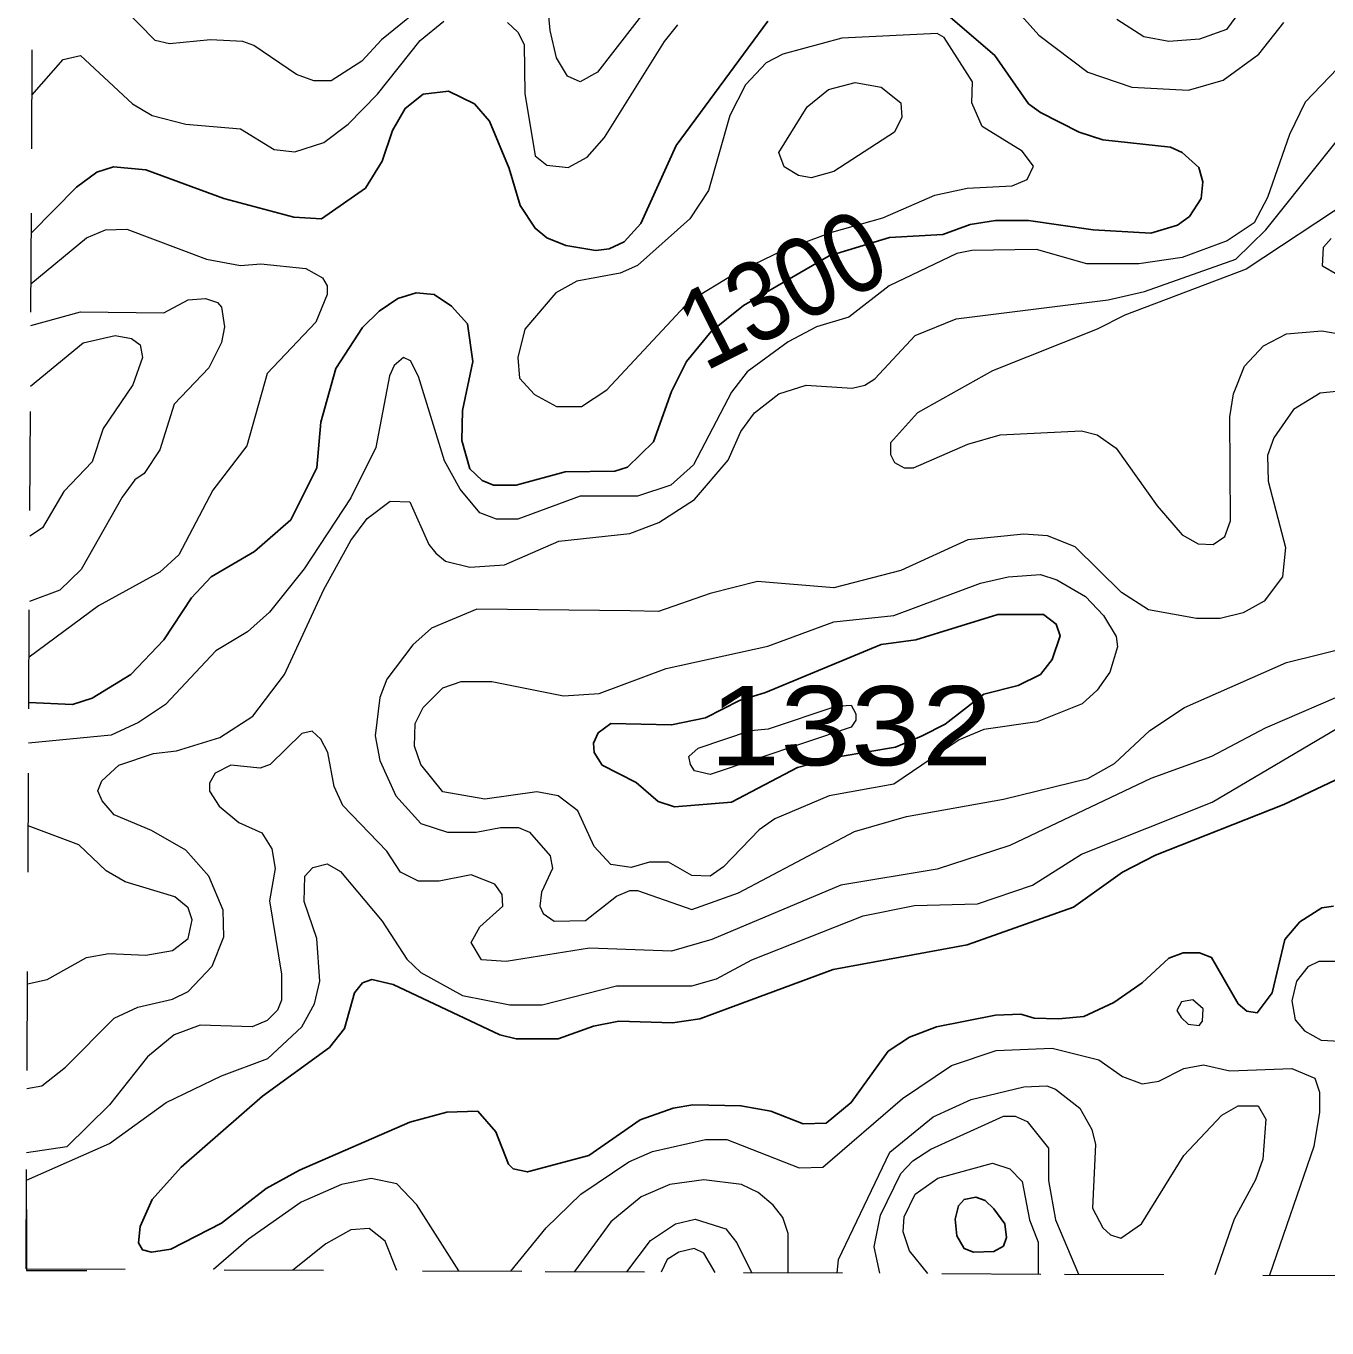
# Model space of a CAD drawing. Extents: x 577 to 602.9, y 7483.8 to 7511.6.
# Drawn here: x 577.007 to 578.319, y 7483.867 to 7485.181 of the extents above; entities that cross this region are included whole.
import ezdxf
from ezdxf.enums import TextEntityAlignment as Align

# ---------------------------------------------------------------- set-up
doc = ezdxf.new("R2010")
doc.units = 0
doc.header["$LTSCALE"] = 0.032
doc.linetypes.add('SHORT_DASHED', pattern=[2.7, 1.5, -1.2])
for name, color, linetype, lineweight in [('1', 7, 'Continuous', 25), ('2', 7, 'Continuous', 13), ('62', 7, 'SHORT_DASHED', 13), ('63', 7, 'Continuous', 13)]:
    doc.layers.add(name, color=color, linetype=linetype, lineweight=lineweight)
doc.layers.add('61', color=7, linetype='Continuous')

msp = doc.modelspace()

# ---------------------------------------------------------------- linework, layer by layer
at = {"layer": '1'}
for points in [[(577.9179, 7485.2079), (577.9839, 7485.1507), (578.0181, 7485.1022), (578.03, 7485.0934), (578.069, 7485.0735), (578.0928, 7485.0656), (578.1612, 7485.0584), (578.1731, 7485.0529), (578.1898, 7485.0377), (578.1938, 7485.0234), (578.1922, 7485.0067), (578.1803, 7484.9884), (578.1684, 7484.9797), (578.1413, 7484.9717), (578.0833, 7484.9749), (578.0181, 7484.9845), (577.9847, 7484.9845), (577.9592, 7484.9805), (577.9314, 7484.9702), (577.8777, 7484.9673), (577.8168, 7484.9486), (577.7304, 7484.8988), (577.698, 7484.8725), (577.673, 7484.8421), (577.6579, 7484.8119), (577.6396, 7484.761), (577.6133, 7484.7356), (577.6006, 7484.7316), (577.5505, 7484.7308), (577.5012, 7484.7173), (577.4782, 7484.7173), (577.467, 7484.7221), (577.4543, 7484.734), (577.4464, 7484.7626), (577.4471, 7484.7928), (577.4575, 7484.8421), (577.4519, 7484.8803), (577.436, 7484.8978), (577.4185, 7484.9097), (577.4002, 7484.9113), (577.3819, 7484.9057), (577.3629, 7484.893), (577.3462, 7484.8763), (577.3191, 7484.835), (577.304, 7484.7809), (577.3, 7484.7348), (577.2738, 7484.6823), (577.2372, 7484.6505), (577.1935, 7484.625), (577.1736, 7484.6036), (577.1458, 7484.5614), (577.1124, 7484.5264), (577.0734, 7484.5026), (577.0535, 7484.4962), (577.0095, 7484.4983)], [(577.012, 7484.9716), (577.0575, 7485.0179), (577.0782, 7485.033), (577.0949, 7485.0385), (577.1275, 7485.0354), (577.2062, 7485.0067), (577.277, 7484.9876), (577.3048, 7484.9861), (577.3493, 7485.0171), (577.366, 7485.0441), (577.3764, 7485.0751), (577.3891, 7485.0974), (577.4074, 7485.1117), (577.4328, 7485.1149), (577.4591, 7485.1022), (577.4742, 7485.0847), (577.4941, 7485.0369), (577.5052, 7484.9996), (577.5203, 7484.9765), (577.5322, 7484.967), (577.5513, 7484.959), (577.5815, 7484.9542), (577.595, 7484.9558), (577.6102, 7484.963), (577.6269, 7484.9813), (577.6626, 7485.06), (577.7549, 7485.1856)], [(578.0101, 7484.1837), (577.9847, 7484.1829), (577.925, 7484.171), (577.898, 7484.1607), (577.8765, 7484.1464), (577.8392, 7484.0947), (577.8137, 7484.074), (577.7907, 7484.0732), (577.7581, 7484.0859), (577.7278, 7484.0915), (577.6793, 7484.0923), (577.6595, 7484.0891), (577.6261, 7484.0772), (577.5744, 7484.0414), (577.5124, 7484.0247), (577.498, 7484.0279), (577.4933, 7484.0326), (577.4805, 7484.0652), (577.4623, 7484.0859), (577.4312, 7484.0851), (577.3939, 7484.0748), (577.2825, 7484.0263), (577.2491, 7484.008), (577.2038, 7483.973), (577.1529, 7483.9468), (577.1331, 7483.9436), (577.1243, 7483.946), (577.1203, 7483.9531), (577.1219, 7483.9698), (577.1338, 7483.9969), (577.1633, 7484.0295), (577.2452, 7484.101), (577.3128, 7484.1503), (577.3279, 7484.1694), (577.3382, 7484.2052), (577.3462, 7484.2155), (577.3557, 7484.2187), (577.3772, 7484.2139), (577.4845, 7484.163), (577.5012, 7484.1591), (577.5434, 7484.1591), (577.5791, 7484.1718), (577.6046, 7484.1766), (577.6587, 7484.175), (577.6865, 7484.179), (577.8209, 7484.229), (577.9561, 7484.2537), (578.0634, 7484.2919), (578.1127, 7484.3269), (578.1461, 7484.3443), (578.2757, 7484.3952), (578.4833, 7484.4938)], [(578.3258, 7484.2927), (578.3139, 7484.2911), (578.2916, 7484.2768), (578.2765, 7484.2593), (578.2638, 7484.2052), (578.2487, 7484.1853), (578.2383, 7484.1869), (578.2296, 7484.1941), (578.2026, 7484.241), (578.1906, 7484.2457), (578.1739, 7484.2457), (578.1596, 7484.2402), (578.1326, 7484.2155), (578.104, 7484.1957), (578.0737, 7484.1813), (578.0483, 7484.179), (578.0236, 7484.1797), (578.0101, 7484.1837)]]:
    msp.add_lwpolyline(points, dxfattribs=at)
for points in [[(577.7527, 7484.5084), (577.8694, 7484.5567), (577.9044, 7484.5614), (577.9871, 7484.5869), (578.0332, 7484.5869), (578.0459, 7484.5773), (578.0499, 7484.5654), (578.0419, 7484.5416), (578.03, 7484.5264), (578.0077, 7484.5153), (577.9728, 7484.5066), (577.9338, 7484.4763), (577.9107, 7484.4644), (577.8837, 7484.4533), (577.828, 7484.4437), (577.7851, 7484.4326), (577.7183, 7484.3976), (577.661, 7484.3929), (577.6443, 7484.3984), (577.6221, 7484.4175), (577.5879, 7484.435), (577.5799, 7484.4477), (577.5791, 7484.4573), (577.5839, 7484.4676), (577.5966, 7484.4771), (577.6579, 7484.4756), (577.6921, 7484.4827), (577.7263, 7484.5002)], [(577.9831, 7483.9873), (577.9741, 7483.9958), (577.9648, 7483.9992), (577.9529, 7483.9969), (577.9473, 7483.9905), (577.9441, 7483.977), (577.9457, 7483.9603), (577.9529, 7483.9476), (577.9624, 7483.9436), (577.9831, 7483.9444), (577.9926, 7483.9499), (577.9958, 7483.9587), (577.9942, 7483.9722)]]:
    msp.add_lwpolyline(points, close=True, dxfattribs=at)
at = {"layer": '2'}
for points in [[(577.9759, 7485.2302), (578.0284, 7485.1713), (578.0777, 7485.134), (578.1222, 7485.1189), (578.1795, 7485.1157), (578.2145, 7485.126), (578.2503, 7485.1522), (578.2757, 7485.1841)], [(577.4169, 7485.2087), (577.3652, 7485.1666), (577.3454, 7485.1451), (577.3144, 7485.1252), (577.2969, 7485.1252), (577.2794, 7485.1316), (577.2364, 7485.161), (577.2253, 7485.165), (577.1927, 7485.1666), (577.1513, 7485.1626), (577.137, 7485.1658), (577.0861, 7485.2182)], [(577.6404, 7485.2079), (577.5831, 7485.134), (577.5656, 7485.1244), (577.5529, 7485.13), (577.5418, 7485.1483), (577.5354, 7485.1761), (577.5314, 7485.2198)], [(578.2328, 7485.1976), (578.2177, 7485.1769), (578.1906, 7485.1674), (578.1596, 7485.165), (578.1342, 7485.1697), (578.1071, 7485.1872)], [(577.0127, 7485.1109), (577.044, 7485.1467), (577.0615, 7485.1507), (577.114, 7485.1022), (577.1338, 7485.0902), (577.168, 7485.0815), (577.2229, 7485.0767), (577.2571, 7485.056), (577.2778, 7485.0536), (577.3072, 7485.0632), (577.3318, 7485.0815), (577.3613, 7485.1117), (577.4042, 7485.1658), (577.4281, 7485.1856)], [(577.4925, 7485.1841), (577.5028, 7485.1745), (577.5092, 7485.1618), (577.51, 7485.1125), (577.5203, 7485.0497), (577.5322, 7485.0401), (577.5537, 7485.0377), (577.5728, 7485.0481), (577.5903, 7485.068), (577.6507, 7485.165), (577.6642, 7485.1817)], [(578.3703, 7485.1801), (578.2972, 7485.1037), (578.2813, 7485.0711), (578.259, 7485.0075), (578.2455, 7484.9821), (578.2185, 7484.9638), (578.1731, 7484.9471), (578.1294, 7484.9407), (578.0769, 7484.9407), (578.026, 7484.955), (577.9608, 7484.9542), (577.9457, 7484.9511), (577.8773, 7484.9185), (577.8368, 7484.8867), (577.8042, 7484.8771), (577.7756, 7484.862), (577.7342, 7484.8318), (577.7183, 7484.8111), (577.6801, 7484.738), (577.6571, 7484.7173), (577.6237, 7484.7062), (577.5656, 7484.7062), (577.5028, 7484.6831), (577.4813, 7484.6831), (577.4646, 7484.6895), (577.4448, 7484.7133), (577.4289, 7484.7419), (577.4026, 7484.827), (577.3947, 7484.8429), (577.3875, 7484.8461), (577.378, 7484.8382), (577.3732, 7484.8278), (577.3597, 7484.7555), (577.3342, 7484.7046), (577.2873, 7484.633), (577.2523, 7484.5893), (577.2301, 7484.5694), (577.1983, 7484.5503), (577.1474, 7484.4962), (577.1203, 7484.4779), (577.0925, 7484.4652), (577.0093, 7484.4571)], [(577.0076, 7484.109), (577.0225, 7484.1114), (577.0464, 7484.1304), (577.0957, 7484.1797), (577.1195, 7484.1909), (577.1545, 7484.1988), (577.1704, 7484.2068), (577.1943, 7484.2322), (577.2062, 7484.2617), (577.2054, 7484.2887), (577.1911, 7484.3229), (577.168, 7484.3491), (577.1331, 7484.369), (577.0957, 7484.3849), (577.0834, 7484.3991), (577.0792, 7484.4091), (577.083, 7484.4191), (577.1004, 7484.435), (577.1354, 7484.4469), (577.1585, 7484.4493), (577.2022, 7484.4628), (577.2356, 7484.4843), (577.2674, 7484.5264), (577.3072, 7484.6123), (577.3342, 7484.6616), (577.3509, 7484.6839), (577.374, 7484.7014), (577.3939, 7484.7006), (577.413, 7484.6576), (577.4201, 7484.6489), (577.4297, 7484.6409), (577.4543, 7484.6346), (577.4893, 7484.637), (577.5442, 7484.6608), (577.6157, 7484.6688), (577.6451, 7484.6799), (577.6809, 7484.703), (577.7151, 7484.7427), (577.7278, 7484.7714), (577.7414, 7484.7904), (577.766, 7484.8095), (577.7938, 7484.8183), (577.84, 7484.8151), (577.8527, 7484.8183), (577.863, 7484.8246), (577.9036, 7484.8684), (577.9449, 7484.8851), (578.0984, 7484.9042), (578.135, 7484.9129), (578.2272, 7484.9455), (578.2574, 7484.9749), (578.3711, 7485.1173)], [(578.3433, 7485.0051), (578.2376, 7484.9352), (578.1151, 7484.889), (578.0873, 7484.8747), (577.9815, 7484.8326), (577.906, 7484.7904), (577.8789, 7484.7602), (577.8789, 7484.7483), (577.8829, 7484.7403), (577.8924, 7484.7348), (577.902, 7484.7348), (577.9569, 7484.7586), (577.9895, 7484.7682), (578.0714, 7484.7722), (578.0873, 7484.7682), (578.1063, 7484.7547), (578.1477, 7484.6966), (578.1731, 7484.6672), (578.189, 7484.6584), (578.2042, 7484.6576), (578.2161, 7484.6656), (578.2216, 7484.6815), (578.2209, 7484.7865), (578.2248, 7484.8095), (578.236, 7484.8374), (578.255, 7484.858), (578.2781, 7484.87), (578.3139, 7484.8731), (578.368, 7484.8636)], [(577.0117, 7484.9206), (577.0678, 7484.967), (577.0869, 7484.9749), (577.1084, 7484.9757), (577.1887, 7484.9455), (577.2229, 7484.9391), (577.2436, 7484.9407), (577.2889, 7484.936), (577.3056, 7484.9264), (577.3104, 7484.9185), (577.3104, 7484.9097), (577.2992, 7484.8819), (577.2499, 7484.8302), (577.2293, 7484.757), (577.1951, 7484.7125), (577.1609, 7484.6473), (577.1418, 7484.6298), (577.0798, 7484.5956), (577.0098, 7484.5439)], [(578.3449, 7484.9209), (578.3147, 7484.9383), (578.3155, 7484.9574), (578.3234, 7484.9662)], [(577.0115, 7484.8783), (577.0615, 7484.8922), (577.1458, 7484.8914), (577.1704, 7484.9042), (577.1879, 7484.9057), (577.1998, 7484.9018), (577.2038, 7484.897), (577.207, 7484.8771), (577.2038, 7484.8612), (577.1911, 7484.8358), (577.1561, 7484.7992), (577.1418, 7484.7531), (577.1259, 7484.7292), (577.1164, 7484.7229), (577.1036, 7484.7054), (577.0623, 7484.6322), (577.0408, 7484.6115), (577.0101, 7484.5999)], [(577.0112, 7484.8174), (577.0642, 7484.8609), (577.0965, 7484.8684), (577.1132, 7484.8652), (577.1219, 7484.8588), (577.1243, 7484.8461), (577.1146, 7484.8185), (577.0845, 7484.7745), (577.0734, 7484.7411), (577.0448, 7484.7109), (577.0233, 7484.6743), (577.0104, 7484.6658)], [(578.3449, 7484.8135), (578.3123, 7484.8103), (578.2853, 7484.7936), (578.2654, 7484.765), (578.259, 7484.7475), (578.2598, 7484.7213), (578.2773, 7484.6545), (578.2741, 7484.625), (578.2558, 7484.6004), (578.2344, 7484.5885), (578.2113, 7484.5829), (578.1875, 7484.5829), (578.1389, 7484.5916), (578.1119, 7484.6091), (578.065, 7484.6553), (578.0372, 7484.6664), (578.0133, 7484.668), (577.9569, 7484.6624), (577.8893, 7484.6314), (577.8217, 7484.6139), (577.7445, 7484.6203), (577.6968, 7484.6083), (577.6448, 7484.5901), (577.6161, 7484.5907), (577.4615, 7484.5924), (577.4156, 7484.5732), (577.3969, 7484.5565), (577.3708, 7484.5217), (577.3637, 7484.5034), (577.3589, 7484.4644), (577.3637, 7484.4398), (577.3796, 7484.404), (577.405, 7484.3762), (577.432, 7484.3674), (577.4607, 7484.3674), (577.4853, 7484.3722), (577.5036, 7484.3722), (577.5147, 7484.3674), (577.5354, 7484.3436), (577.5378, 7484.3308), (577.5267, 7484.307), (577.5251, 7484.2927), (577.5283, 7484.2855), (577.5394, 7484.2776), (577.5712, 7484.2783), (577.6022, 7484.303), (577.6157, 7484.3086), (577.6237, 7484.3086), (577.6785, 7484.2895), (577.7255, 7484.3062), (577.8423, 7484.3682), (577.8948, 7484.3833), (577.9926, 7484.4008), (578.0777, 7484.4215), (578.1048, 7484.4366), (578.1405, 7484.47), (578.1755, 7484.493), (578.2781, 7484.5384), (578.3449, 7484.5551)], [(578.3473, 7484.5113), (578.2566, 7484.4724), (578.2026, 7484.4437), (578.1413, 7484.4215), (577.999, 7484.3539), (577.9258, 7484.33), (577.8288, 7484.3141), (577.6984, 7484.2593), (577.6579, 7484.2473), (577.5752, 7484.2505), (577.4909, 7484.237), (577.4662, 7484.2386), (577.4559, 7484.2561), (577.4646, 7484.272), (577.4877, 7484.2927), (577.4869, 7484.3046), (577.4797, 7484.3149), (577.4559, 7484.3245), (577.4233, 7484.3181), (577.4026, 7484.3181), (577.3843, 7484.3269), (577.3708, 7484.3483), (577.3263, 7484.3944), (577.3175, 7484.4135), (577.3112, 7484.4477), (577.304, 7484.4612), (577.2953, 7484.4692), (577.2849, 7484.4668), (577.2531, 7484.4358), (577.2428, 7484.4318), (577.2134, 7484.435), (577.1975, 7484.427), (577.1919, 7484.4167), (577.1919, 7484.4088), (577.2014, 7484.3936), (577.2213, 7484.377), (577.2444, 7484.3666), (577.2547, 7484.3507), (577.2579, 7484.3308), (577.2523, 7484.2982), (577.2643, 7484.2243), (577.2643, 7484.198), (577.2603, 7484.1877), (577.2499, 7484.1774), (577.2348, 7484.171), (577.1824, 7484.1726), (577.1561, 7484.163), (577.1291, 7484.1408), (577.0909, 7484.0923), (577.048, 7484.0501), (577.0073, 7484.0439)], [(577.0071, 7484.0164), (577.0909, 7484.0533), (577.1482, 7484.0947), (577.2038, 7484.1217), (577.2507, 7484.1392), (577.2849, 7484.171), (577.2977, 7484.1941), (577.3032, 7484.2171), (577.3, 7484.2601), (577.2873, 7484.2974), (577.2881, 7484.3229), (577.2961, 7484.3316), (577.3104, 7484.3356), (577.3239, 7484.3277), (577.366, 7484.2776), (577.3907, 7484.2394), (577.405, 7484.2259), (577.4471, 7484.2028), (577.4949, 7484.1933), (577.5275, 7484.1933), (577.6022, 7484.2123), (577.6785, 7484.2123), (577.7032, 7484.2195), (577.739, 7484.2386), (577.8511, 7484.2831), (577.9028, 7484.2935), (577.9664, 7484.295), (578.0221, 7484.3141), (578.0714, 7484.3451), (578.2034, 7484.3976), (578.3298, 7484.4724)], [(577.0081, 7484.2143), (577.0281, 7484.2187), (577.0678, 7484.241), (577.0901, 7484.245), (577.1275, 7484.2434), (577.1545, 7484.2481), (577.1704, 7484.2601), (577.1744, 7484.2791), (577.1704, 7484.2911), (577.1569, 7484.3022), (577.1068, 7484.3173), (577.0877, 7484.3284), (577.0599, 7484.3547), (577.0089, 7484.3739)], [(577.4957, 7483.9245), (577.5314, 7483.9682), (577.5664, 7484.0024), (577.6149, 7484.035), (577.6388, 7484.0454), (577.6921, 7484.0573), (577.7135, 7484.0573), (577.7867, 7484.0287), (577.8105, 7484.0295), (577.8909, 7484.0986), (577.9402, 7484.132), (577.9855, 7484.1471), (578.0419, 7484.1495), (578.0889, 7484.1376), (578.1127, 7484.1209), (578.1326, 7484.1137), (578.1493, 7484.1161), (578.1747, 7484.1289), (578.1946, 7484.1328), (578.2209, 7484.1265), (578.2837, 7484.1289), (578.3067, 7484.1193), (578.3115, 7484.105), (578.3115, 7484.0851), (578.3057, 7484.0505), (578.2612, 7483.9206)], [(577.825, 7483.9227), (577.8264, 7483.9364), (577.8781, 7484.0446), (577.9219, 7484.0804), (577.96, 7484.0978), (578.0133, 7484.1106), (578.0364, 7484.1114), (578.0451, 7484.1082), (578.0698, 7484.0891), (578.0817, 7484.0676), (578.0857, 7484.0525), (578.0825, 7483.9881), (578.0928, 7483.9682), (578.1008, 7483.9611), (578.1111, 7483.9579), (578.1318, 7483.9722), (578.1747, 7484.0414), (578.2129, 7484.0819), (578.2296, 7484.0915), (578.2495, 7484.0915), (578.2574, 7484.078), (578.2542, 7484.0374), (578.2471, 7484.0167), (578.2256, 7483.977), (578.206, 7483.9208)], [(577.868, 7483.9225), (577.8622, 7483.9491), (577.8686, 7483.981), (577.8893, 7484.0231), (577.9012, 7484.0358), (577.9195, 7484.0477), (577.9926, 7484.0811), (578.0046, 7484.0811), (578.0165, 7484.0756), (578.038, 7484.0485), (578.038, 7484.0159), (578.0451, 7483.9762), (578.0685, 7483.9215)], [(577.9163, 7483.9223), (577.898, 7483.9452), (577.8916, 7483.9643), (577.8924, 7483.9794), (577.9036, 7484.0024), (577.9266, 7484.0183), (577.9815, 7484.0334), (577.999, 7484.0279), (578.0117, 7484.0151), (578.0189, 7483.9762), (578.0276, 7483.9539), (578.0276, 7483.9217)], [(577.4434, 7483.9248), (577.4009, 7483.9915), (577.3809, 7484.0128), (577.3549, 7484.0181), (577.325, 7484.0121), (577.2844, 7483.9942), (577.2311, 7483.9569), (577.1958, 7483.9262)], [(577.7756, 7483.923), (577.7756, 7483.9627), (577.77, 7483.9786), (577.7604, 7483.9913), (577.7453, 7484.004), (577.7286, 7484.012), (577.6905, 7484.0167), (577.6563, 7484.012), (577.6271, 7483.9995), (577.5967, 7483.9742), (577.5601, 7483.9241)], [(577.6127, 7483.9239), (577.6366, 7483.9555), (577.6619, 7483.9724), (577.6817, 7483.977), (577.7127, 7483.9674), (577.7239, 7483.9531), (577.7387, 7483.9232)], [(577.3809, 7483.9252), (577.3689, 7483.9549), (577.3529, 7483.9675), (577.3343, 7483.9662), (577.309, 7483.9522), (577.2757, 7483.9257)], [(577.7019, 7483.9234), (577.6905, 7483.9429), (577.6806, 7483.9475), (577.6652, 7483.9436), (577.6533, 7483.9362), (577.6473, 7483.9237)]]:
    msp.add_lwpolyline(points, dxfattribs=at)
for points in [[(577.871, 7484.9869), (577.9235, 7485.0099), (577.9561, 7485.0171), (578.0014, 7485.0195), (578.0165, 7485.0258), (578.0229, 7485.0393), (578.0117, 7485.0544), (577.9712, 7485.0791), (577.9608, 7485.1029), (577.9616, 7485.1244), (577.933, 7485.1689), (577.9258, 7485.1729), (577.8296, 7485.1682), (577.77, 7485.1522), (577.7533, 7485.1435), (577.7326, 7485.1212), (577.7167, 7485.0902), (577.6952, 7485.0147), (577.6762, 7484.9861), (577.6237, 7484.9391), (577.6062, 7484.9312), (577.5624, 7484.9232), (577.541, 7484.9113), (577.51, 7484.8747), (577.5028, 7484.8461), (577.5044, 7484.8254), (577.5195, 7484.8087), (577.5418, 7484.7968), (577.5672, 7484.7968), (577.5927, 7484.8135), (577.6762, 7484.9034), (577.7218, 7484.9308), (577.7698, 7484.954), (577.8196, 7484.9727)], [(577.8161, 7485.1165), (577.8431, 7485.1236), (577.8694, 7485.1189), (577.8893, 7485.1029), (577.8901, 7485.0886), (577.8829, 7485.0735), (577.8217, 7485.0338), (577.7986, 7485.0274), (577.7859, 7485.0298), (577.7716, 7485.0385), (577.766, 7485.0529), (577.7946, 7485.099)], [(577.8217, 7484.5797), (577.8821, 7484.5861), (577.9696, 7484.6187), (577.9974, 7484.625), (578.03, 7484.6274), (578.0467, 7484.6219), (578.0753, 7484.6052), (578.0936, 7484.5861), (578.1063, 7484.5646), (578.1079, 7484.5543), (578.1, 7484.5288), (578.0873, 7484.5105), (578.0722, 7484.497), (578.0268, 7484.4787), (577.9728, 7484.4708), (577.9481, 7484.4604), (577.8821, 7484.4159), (577.8169, 7484.404), (577.762, 7484.3809), (577.7461, 7484.3698), (577.7103, 7484.3324), (577.6968, 7484.3229), (577.6785, 7484.3237), (577.6547, 7484.3372), (577.6356, 7484.3372), (577.6173, 7484.3316), (577.5966, 7484.3348), (577.5799, 7484.3531), (577.5632, 7484.3889), (577.5434, 7484.404), (577.5219, 7484.408), (577.4694, 7484.4008), (577.4273, 7484.408), (577.405, 7484.4358), (577.3986, 7484.4541), (577.3994, 7484.4771), (577.4074, 7484.493), (577.4273, 7484.5129), (577.4456, 7484.5193), (577.4766, 7484.5193), (577.5489, 7484.505), (577.5847, 7484.5074), (577.6524, 7484.5326), (577.7549, 7484.5549)], [(577.8392, 7484.4954), (577.8439, 7484.4867), (577.8439, 7484.4803), (577.8392, 7484.4732), (577.6968, 7484.4255), (577.6809, 7484.4294), (577.6769, 7484.4358), (577.6754, 7484.4437), (577.6848, 7484.4522), (577.7374, 7484.47), (577.7557, 7484.4716), (577.8241, 7484.4946)], [(578.3465, 7484.163), (578.3552, 7484.1718), (578.3584, 7484.1805), (578.3592, 7484.2052), (578.3552, 7484.2147), (578.3409, 7484.2314), (578.3274, 7484.237), (578.3107, 7484.237), (578.2996, 7484.2314), (578.2884, 7484.2171), (578.2837, 7484.1972), (578.2869, 7484.1782), (578.2964, 7484.167), (578.3131, 7484.1575), (578.3322, 7484.1567)], [(578.1719, 7484.1803), (578.1792, 7484.1736), (578.19, 7484.1725), (578.1935, 7484.1768), (578.1942, 7484.1891), (578.1839, 7484.1982), (578.1723, 7484.1964), (578.1677, 7484.1876)]]:
    msp.add_lwpolyline(points, close=True, dxfattribs=at)
at = {"layer": '62'}
for points in [[(577.0067, 7483.927), (577.0095, 7484.4918), (577.0124, 7485.0566), (577.0152, 7485.6214), (577.0181, 7486.1863), (577.0209, 7486.7511), (577.0238, 7487.3159), (577.0267, 7487.8807), (577.0295, 7488.4455), (577.0324, 7489.0103), (577.0352, 7489.5752), (577.0381, 7490.14), (577.0409, 7490.7048), (577.0438, 7491.2696), (577.0466, 7491.8344), (577.0495, 7492.3992), (577.0523, 7492.9641)], [(577.0067, 7483.927), (577.5305, 7483.9243), (578.0544, 7483.9216), (578.5783, 7483.9189), (579.1022, 7483.9162), (579.626, 7483.9135), (580.1499, 7483.9107), (580.6738, 7483.908), (581.1977, 7483.9052), (581.7216, 7483.9024), (582.2454, 7483.8996), (582.7693, 7483.8967), (583.2932, 7483.8938), (583.8171, 7483.891), (584.341, 7483.8881), (584.8649, 7483.8852), (585.3887, 7483.8822), (585.9126, 7483.8793), (586.4365, 7483.8763), (586.9604, 7483.8733), (587.4843, 7483.8703), (588.0082, 7483.8673)]]:
    msp.add_lwpolyline(points, dxfattribs=at)
at = {"layer": '63'}
msp.add_lwpolyline([(577.0072, 7483.9868), (577.0072, 7483.9252), (577.0679, 7483.9252)], dxfattribs=at)

# ---------------------------------------------------------------- texts
at = {"layer": '61', "width": 0.9}
msp.add_text('1300', height=0.08, rotation=26.685, dxfattribs=at).set_placement((577.7872, 7484.8798), align=Align.CENTER)
at = {"layer": '61', "width": 1.2}
msp.add_text('1332', height=0.08, dxfattribs=at).set_placement((577.8388, 7484.4348), align=Align.CENTER)

doc.saveas('drawing.dxf')
